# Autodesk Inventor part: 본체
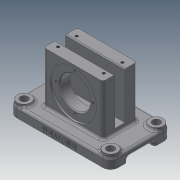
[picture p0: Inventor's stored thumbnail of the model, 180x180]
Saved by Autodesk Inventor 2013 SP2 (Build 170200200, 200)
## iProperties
Created: 2025-04
Part Number: 본체
Material: Generic
Document SubType Name: Modeling
Designer: i
Density: 1 g/cm^3
Author: i
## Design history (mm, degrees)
sketch "스케치1"
  geometry: L1 (-35, 20)-(35, 20); L2 (35, 20)-(35, -20); L3 (35, -20)-(-35, -20); L4 (-35, -20)-(-35, 20); L5 (-35, 20)-(35, -20); L6 (35, 20)-(-35, -20); 1 further point
  constraints: 12 end point, 2 midpoint, 2 parallel, 1 horizontal, 1 perpendicular
  dimensions: "d0" = 70 distance of L2.end L3.end; "d2" = 40 distance of L3.end L1.start
extrude "돌출1" new body sketch "스케치1" distance "d3" = 72; taper "d4" = 0 deg
sketch "스케치2"
  geometry: L1 (35, 20)-(-35, 20) reference; L2 (-35, 20)-(-35, -20) reference; L3 (-35, -20)-(35, -20) reference; L4 (35, -20)-(35, 20) reference; L5 (-60, 36)-(60, 36); L6 (60, 36)-(60, -36); L7 (60, -36)-(-60, -36); L8 (-60, -36)-(-60, 36); L9 (-60, 36)-(60, -36); L10 (60, 36)-(-60, -36); 1 further point
  constraints: 12 end point, 2 midpoint, 2 parallel, 1 horizontal, 1 perpendicular
  dimensions: "d5" = 120 distance of L6.end L7.end; "d7" = 72 distance of L7.end L5.start
extrude "돌출2" join sketch "스케치2" distance "d8" = 12; taper "d9" = 0 deg
fillet "모깎기1" dims "d10" = 9
sketch "스케치3"
  geometry: C1 r 8 at (51, -27); A1 r 9 centre (51, -27) between (51, -36) and (60, -27) reference; 1 further point
  constraints: 1 centre point, 1 coincident
  dimensions: "d11" = 16 diameter of C1
extrude "돌출3" join sketch "스케치3" distance "d12" = 3; taper "d13" = 0 deg
sketch "스케치4"
  geometry: C1 r 8 at (0, 0) reference; C2 r 4.5 at (0, 0); 1 further point
  constraints: 1 centre point, 1 coincident
  dimensions: "d14" = 9 diameter of C2
extrude "돌출4" cut sketch "스케치4" stored distance "d15" = 3; taper "d16" = 0 deg
sketch "스케치5"
  geometry: L1 (0, 0)-(54, 0) reference; L2 (11, 5)-(43, 5); L3 (43, 5)-(43, 0); L4 (43, 0)-(11, 0); L5 (11, 0)-(11, 5); 2 further points
  constraints: 8 end point, 2 midpoint, 2 parallel, 1 horizontal, 1 perpendicular
  dimensions: "d17" = 32 distance of L2.start L2.end; "d19" = 5 distance of L2.end L3.end
extrude "돌출5" cut sketch "스케치5" stored distance "d20" = 3; taper "d21" = 0 deg
sketch "스케치6"
  geometry: L1 (70, 0)-(0, 0) reference; L2 (-16, -72)-(86, -72) reference; C1 r 17 at (35, -30); 2 further points
  constraints: 1 centre point, 1 midpoint, 1 vertical alignment
  dimensions: "d22" = 34 diameter of C1; "d23" = 42 distance from line of L2 C1.centre
extrude "돌출6" join sketch "스케치6" distance "d24" = 7; taper "d25" = 0 deg
sketch "스케치7"
  geometry: C1 r 17 at (0, 0) reference; C2 r 11 at (0, 0); 1 further point
  constraints: 1 centre point, 1 coincident
  dimensions: "d26" = 22 diameter of C2
extrude "돌출7" cut sketch "스케치7" stored distance "d27" = 7; taper "d28" = 0 deg
sketch "스케치8"
  geometry: L1 (40, 0)-(0, 0) reference; L2 (14, 0)-(26, 0); L3 (26, 0)-(26, -55); L4 (26, -55)-(14, -55); L5 (14, -55)-(14, 0); 2 further points
  constraints: 8 end point, 2 midpoint, 2 parallel, 1 horizontal, 1 perpendicular
  dimensions: "d29" = 12 distance of L3.end L4.end; "d31" = 55 distance of L2.end L3.end
extrude "돌출8" cut sketch "스케치8" stored distance "d32" = 7; taper "d33" = 0 deg
sketch "스케치9"
  geometry: C1 r 11 at (35, 25) reference; C2 r 15 at (35, 25); 1 further point
  constraints: 1 centre point, 1 coincident
  dimensions: "d34" = 30 diameter of C2
extrude "돌출9" cut sketch "스케치9" distance "d35" = 5; taper "d36" = 0 deg
sketch "스케치10"
  geometry: C1 r 11 at (35, -30) reference; C2 r 27.5 at (35, -30); 1 further point
  constraints: 1 centre point, 1 coincident
  dimensions: "d37" = 55 diameter of C2
extrude "돌출10" cut sketch "스케치10" distance "d38" = 2; taper "d39" = 0 deg
sketch "스케치11"
  geometry: C1 r 11 at (0, 0) reference; C2 r 27.5 at (0, 0) reference; C3 r 18 at (0, 0); 1 further point
  constraints: 1 centre point, 1 coincident
  dimensions: "d40" = 36 diameter of C3
extrude "돌출11" cut sketch "스케치11" stored distance "d41" = 2; taper "d42" = 0 deg
sketch "스케치12" dims "d43" = 44
  geometry: C1 r 27.5 at (0, 0) reference; 3 further points
  constraints: 2 vertical alignment, 1 coincident, 2 other
hole "구멍1" sketch "스케치12" at (0, 22) diameter "d44" = 3.242; stored, may be unused: countersink angle "d48" = 90 deg, drill point angle "d50" = 118 deg; dims "d45" = 8, "d46" = 4, "d47" = 2, "d49" = 10
sketch "스케치13"
  geometry: 5 further points
  constraints: 2 horizontal alignment, 2 vertical alignment
  dimensions: "d54" = 54 distance of point (27, 11) point (-27, 11); "d56" = 27 horizontal distance of point (0, 0) point (-27, 11); "d57" = 22 distance of point (-27, -11) point (-27, 11); "d58" = 11 vertical distance of point (0, 0) point (-27, -11)
hole "구멍2" sketch "스케치13" at (-27, 11), (27, 11), (27, -11), (-27, -11) diameter "d59" = 3.242; stored, may be unused: countersink angle "d63" = 90 deg, drill point angle "d65" = 118 deg; dims "d60" = 8, "d61" = 4, "d62" = 2, "d64" = 10
node "작업 평면1"
sketch "스케치14"
  geometry: L1 (111, 0)-(102, 0) reference; 2 further points
  constraints: 1 vertical alignment, 1 other
  dimensions: "d67" = 5 distance from line of L1 point (51, 5)
feature "엠보싱1" sketch "스케치14" dims "d0" = 70, "d2" = 40, "d68" = 0.5, "d69" = 0
fillet "모깎기2" dims "d70" = 3
fillet "모깎기3" dims "d71" = 3
fillet "모깎기5" dims "d73" = 3
fillet "모깎기6" dims "d74" = 3
fillet "모깎기7" dims "d75" = 3
fillet "모깎기8" dims "d76" = 3
fillet "모깎기9" dims "d77" = 3
chamfer "모따기1" distance "d78" = 1; stored, may be unused: second distance "d79" = 2, angle "d80" = 45 deg
chamfer "모따기2" distance "d81" = 1; stored, may be unused: second distance "d82" = 2, angle "d83" = 45 deg
chamfer "모따기3" distance "d84" = 1; stored, may be unused: second distance "d85" = 2, angle "d86" = 45 deg
node "솔리드1"
mirror "대칭1"
mirror "대칭2"
pattern_circular "원형 패턴1" dims angle "d52" = 360 deg
other parameters: "d66" = 13
